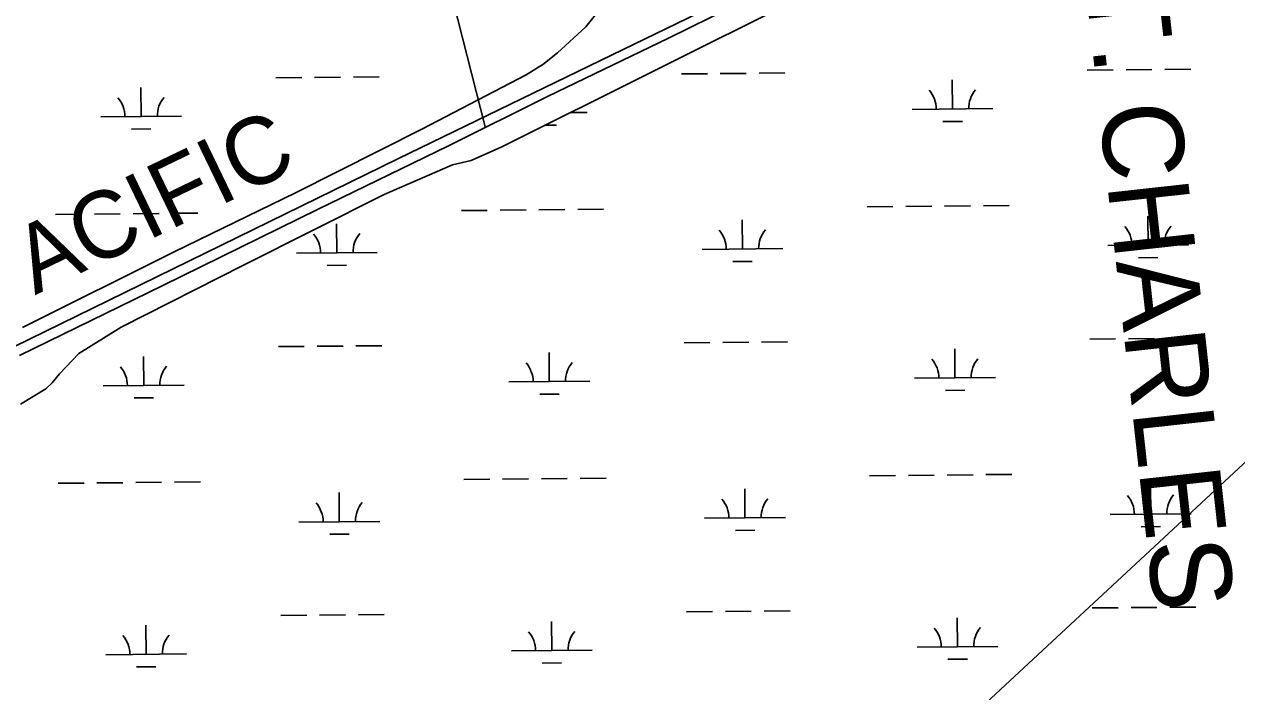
# Model space of a CAD drawing. Extents: x 3598634 to 3636690, y 517270 to 542944.
# Drawn here: x 3614405 to 3615905, y 524173 to 524998 of the extents above; entities that cross this region are included whole.
import ezdxf

# ---------------------------------------------------------------- set-up
doc = ezdxf.new("R2010")
doc.units = 0
for name, color, linetype in [('V-RAIL-IDEN', 7, 'Continuous'), ('V-RAIL-TRAK', 7, 'Continuous'), ('V-ROAD-CNTR', 7, 'Continuous'), ('V-TOPO-GNAM-IDEN', 7, 'Continuous'), ('V-TOPO-SHOR', 7, 'Continuous'), ('V-UTIL-LINE', 7, 'Continuous'), ('V-WETL-SWMP', 7, 'Continuous')]:
    doc.layers.add(name, color=color, linetype=linetype)

msp = doc.modelspace()

# ---------------------------------------------------------------- linework, layer by layer
at = {"layer": 'V-RAIL-TRAK'}
for points in [[(3616601.5, 525563.1), (3616503.1, 525533.5), (3616383.3, 525495.8), (3616275.5, 525458.8), (3616180.7, 525425), (3616102.4, 525395.3), (3616017.2, 525362.4), (3615906.1, 525315.8), (3615787.8, 525264.5), (3615665.5, 525207.6), (3615547.4, 525150.5), (3615459, 525107.8), (3615360.2, 525058.9), (3615202.4, 524981.2)], [(3615202.4, 524981.2), (3615052.9, 524908.8), (3614930.4, 524847.9), (3614768.9, 524769.6), (3614576.7, 524675.1), (3614399.4, 524588.7)]]:
    msp.add_lwpolyline(points, dxfattribs=at)
at = {"layer": 'V-ROAD-CNTR'}
msp.add_lwpolyline([(3615846.2, 525306.6), (3615159.9, 524973.8), (3614867.6, 524832), (3614450.7, 524627.6), (3614081.3, 524447.1), (3613503.9, 524166), (3613020.6, 523930.2), (3612510.7, 523681.4), (3611965.7, 523412.5), (3611456.5, 523159.5), (3610677.5, 522777.3), (3610628.2, 522752.6)], dxfattribs=at)
at = {"layer": 'V-TOPO-SHOR'}
msp.add_lwpolyline([(3614975.5, 524871.3), (3614880.2, 525245.7), (3613884.9, 529162)], dxfattribs=at)
at = {"layer": 'V-UTIL-LINE'}
msp.add_lwpolyline([(3614112.1, 522781.8), (3616525.5, 525022.3), (3616499.2, 525513.8), (3616279.6, 530563.6), (3616549.2, 530561.7)], dxfattribs=at)
at = {"layer": 'V-WETL-SWMP'}
for p, q in [((3614996.4, 524846.6), (3615454.7, 525075.6)), ((3614716.7, 524932.2), (3614748.7, 524932.5)), ((3614764.7, 524932.6), (3614796.7, 524932.9)), ((3614812.7, 524933.1), (3614844.7, 524933.4)), ((3615218.6, 524936.9), (3615250.6, 524937.2)), ((3615266.6, 524937.3), (3615298.6, 524937.6)), ((3615314.6, 524937.8), (3615346.6, 524938.1)), ((3615720.5, 524941.5), (3615752.5, 524941.8)), ((3615768.5, 524942), (3615800.5, 524942.3)), ((3615816.5, 524942.4), (3615848.5, 524942.7)), ((3614550.1, 524884.2), (3614549.7, 524920.2)), ((3615553.8, 524893.5), (3615553.5, 524929.5)), ((3615081.5, 524889.2), (3615101.9, 524889.3)), ((3615503.8, 524893.1), (3615603.8, 524894)), ((3614500.1, 524883.7), (3614600.1, 524884.7)), ((3615050, 524873.4), (3615064.1, 524873.6)), ((3615542, 524878), (3615566, 524878.2)), ((3614538.2, 524868.7), (3614562.2, 524868.9)), ((3614958.4, 524829.9), (3614996.4, 524846.6)), ((3614935.2, 524824.3), (3614958.4, 524829.9)), ((3614850.6, 524787.9), (3614935.2, 524824.3)), ((3614676.7, 524700.3), (3614850.6, 524787.9)), ((3614946.2, 524767.8), (3614978.2, 524768.1)), ((3614994.2, 524768.3), (3615026.2, 524768.6)), ((3615042.2, 524768.7), (3615074.2, 524769)), ((3615090.2, 524769.2), (3615122.2, 524769.5)), ((3615448.1, 524772.5), (3615480.1, 524772.8)), ((3615496.1, 524772.9), (3615528.1, 524773.2)), ((3615544.1, 524773.4), (3615576.1, 524773.7)), ((3615592.1, 524773.8), (3615624.1, 524774.1)), ((3614444.3, 524763.2), (3614476.3, 524763.5)), ((3614492.3, 524763.6), (3614524.3, 524763.9)), ((3614540.3, 524764), (3614572.3, 524764.3)), ((3614588.3, 524764.5), (3614620.3, 524764.8)), ((3614792.1, 524715.6), (3614791.8, 524751.6)), ((3615294, 524720.3), (3615293.7, 524756.3)), ((3615795.9, 524725), (3615795.6, 524761)), ((3615244, 524719.8), (3615344, 524720.8)), ((3615745.9, 524724.5), (3615845.9, 524725.4)), ((3614742.1, 524715.2), (3614842.1, 524716.1)), ((3615784, 524709.4), (3615808, 524709.7)), ((3614525.5, 524623.8), (3614676.7, 524700.3)), ((3614780.3, 524700.1), (3614804.3, 524700.3)), ((3615282.1, 524704.8), (3615306.1, 524705)), ((3614473.1, 524591.2), (3614525.5, 524623.8)), ((3614767.8, 524600), (3614799.8, 524600.3)), ((3614815.8, 524600.4), (3614847.8, 524600.7)), ((3615221.7, 524604.2), (3615253.7, 524604.5)), ((3615269.7, 524604.6), (3615301.7, 524604.9)), ((3615317.7, 524605.1), (3615349.7, 524605.4)), ((3615723.6, 524608.9), (3615755.6, 524609.2)), ((3615771.6, 524609.3), (3615803.6, 524609.6)), ((3615819.6, 524609.8), (3615851.6, 524610.1)), ((3614449.1, 524565.7), (3614473.1, 524591.2)), ((3614553.2, 524551.5), (3614552.8, 524587.5)), ((3614719.8, 524599.5), (3614751.8, 524599.8)), ((3615055, 524556.2), (3615054.7, 524592.2)), ((3615556.9, 524560.9), (3615556.6, 524596.9)), ((3614440.1, 524554.8), (3614449.1, 524565.7)), ((3615005.1, 524555.8), (3615105, 524556.7)), ((3615506.9, 524560.4), (3615606.9, 524561.4)), ((3614400.8, 524528.4), (3614432, 524547.3)), ((3614432, 524547.3), (3614440.1, 524554.8)), ((3614503.2, 524551.1), (3614603.2, 524552)), ((3615043.2, 524540.7), (3615067.2, 524540.9)), ((3615545.1, 524545.3), (3615569.1, 524545.6)), ((3614541.3, 524536), (3614565.3, 524536.2)), ((3614949.3, 524435.2), (3614981.3, 524435.5)), ((3614997.3, 524435.6), (3615029.3, 524435.9)), ((3615045.3, 524436), (3615077.3, 524436.3)), ((3615093.3, 524436.5), (3615125.3, 524436.8)), ((3615451.2, 524439.8), (3615483.2, 524440.1)), ((3615499.2, 524440.3), (3615531.2, 524440.6)), ((3615547.2, 524440.7), (3615579.2, 524441)), ((3615595.2, 524441.2), (3615627.2, 524441.5)), ((3614447.4, 524430.5), (3614479.4, 524430.8)), ((3614495.4, 524430.9), (3614527.4, 524431.2)), ((3614543.4, 524431.4), (3614575.4, 524431.7)), ((3614591.4, 524431.8), (3614623.4, 524432.1)), ((3615297.1, 524387.6), (3615296.8, 524423.6)), ((3615799, 524392.3), (3615798.7, 524428.3)), ((3614795.2, 524383), (3614794.9, 524419)), ((3615749, 524391.9), (3615849, 524392.8)), ((3614745.2, 524382.5), (3614845.2, 524383.4)), ((3615247.1, 524387.2), (3615347.1, 524388.1)), ((3615787.1, 524376.8), (3615811.1, 524377)), ((3614783.4, 524367.4), (3614807.4, 524367.7)), ((3615285.2, 524372.1), (3615309.2, 524372.3)), ((3615224.8, 524271.5), (3615256.8, 524271.8)), ((3615272.8, 524272), (3615304.8, 524272.3)), ((3615320.8, 524272.4), (3615352.8, 524272.7)), ((3615726.7, 524276.2), (3615758.7, 524276.5)), ((3615774.7, 524276.7), (3615806.7, 524277)), ((3615822.7, 524277.1), (3615854.7, 524277.4)), ((3614722.9, 524266.9), (3614754.9, 524267.2)), ((3614770.9, 524267.3), (3614802.9, 524267.6)), ((3614818.9, 524267.8), (3614850.9, 524268.1)), ((3615058.1, 524223.6), (3615057.8, 524259.6)), ((3615560, 524228.2), (3615559.7, 524264.2)), ((3614556.3, 524218.9), (3614555.9, 524254.9)), ((3615510, 524227.8), (3615610, 524228.7)), ((3614506.3, 524218.4), (3614606.3, 524219.3)), ((3615008.1, 524223.1), (3615108.1, 524224)), ((3615548.2, 524212.7), (3615572.2, 524212.9)), ((3614544.4, 524203.3), (3614568.4, 524203.6)), ((3615046.3, 524208), (3615070.3, 524208.2))]:
    msp.add_line(p, q, dxfattribs=at)
msp.add_lwpolyline([(3615149, 525056.7), (3615100.3, 524995.2), (3615065.2, 524962.8), (3615047.1, 524948.4), (3615026.3, 524935.6), (3614897.3, 524868.4), (3614741, 524789.9), (3614590.9, 524716.9), (3614403.4, 524623)], dxfattribs=at)
for centre, start, end in [((3615498.6, 524893.5), 359.7615, 41.3052), ((3615609.1, 524894.5), 139.7615, 181.3052), ((3614494.8, 524884.2), 359.7615, 41.3052), ((3614605.3, 524885.2), 139.7615, 181.3052), ((3614736.9, 524715.6), 359.7615, 41.3052), ((3614847.4, 524716.6), 139.7615, 181.3052), ((3615238.8, 524720.3), 359.7615, 41.3052), ((3615349.2, 524721.3), 139.7615, 181.3052), ((3615740.6, 524724.9), 359.7615, 41.3052), ((3615851.1, 524726), 139.7615, 181.3052), ((3614497.9, 524551.5), 359.7615, 41.3052), ((3614608.4, 524552.5), 139.7615, 181.3052), ((3614999.8, 524556.2), 359.7615, 41.3052), ((3615110.3, 524557.2), 139.7615, 181.3052), ((3615501.7, 524560.8), 359.7615, 41.3052), ((3615612.2, 524561.9), 139.7615, 181.3052), ((3614740, 524382.9), 359.7615, 41.3052), ((3614850.4, 524384), 139.7615, 181.3052), ((3615241.9, 524387.6), 359.7615, 41.3052), ((3615352.3, 524388.6), 139.7615, 181.3052), ((3615743.7, 524392.3), 359.7615, 41.3052), ((3615854.2, 524393.3), 139.7615, 181.3052), ((3614501, 524218.8), 359.7615, 41.3052), ((3614611.5, 524219.9), 139.7615, 181.3052), ((3615002.9, 524223.5), 359.7615, 41.3052), ((3615113.4, 524224.5), 139.7615, 181.3052), ((3615504.8, 524228.2), 359.7615, 41.3052), ((3615615.3, 524229.2), 139.7615, 181.3052)]:
    msp.add_arc(centre, 35.2, start, end, dxfattribs=at)

# ---------------------------------------------------------------- texts
at = {"layer": 'V-RAIL-IDEN'}
msp.add_text('PACIFIC', height=83, rotation=25.7628, dxfattribs=at).set_placement((3614352, 524630.8))
at = {"layer": 'V-TOPO-GNAM-IDEN'}
msp.add_text('ST. CHARLES', height=100, rotation=276.2906, dxfattribs=at).set_placement((3615707.8, 525140.6))

doc.saveas('drawing.dxf')
